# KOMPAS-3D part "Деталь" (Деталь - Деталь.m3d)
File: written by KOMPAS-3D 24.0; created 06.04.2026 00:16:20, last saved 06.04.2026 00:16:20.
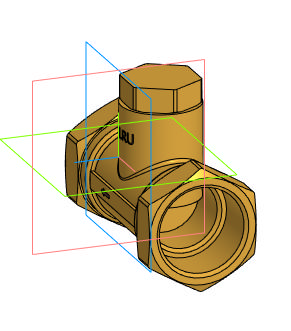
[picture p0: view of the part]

Document properties: Автор: tyuri; Полное имя файла: D:\Аутсорс\Клапан балансировочный автоматический DN.ru VBA0000E-T Ду15 Ру16\DN20\Исходные файлы\Деталь - Деталь.m3d

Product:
- Body: Твердое тело1  | qty 1
- Part/product: Деталь
    additional columns: Типовые

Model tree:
1. Твердое тело1  (labels: Твердое тело1)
